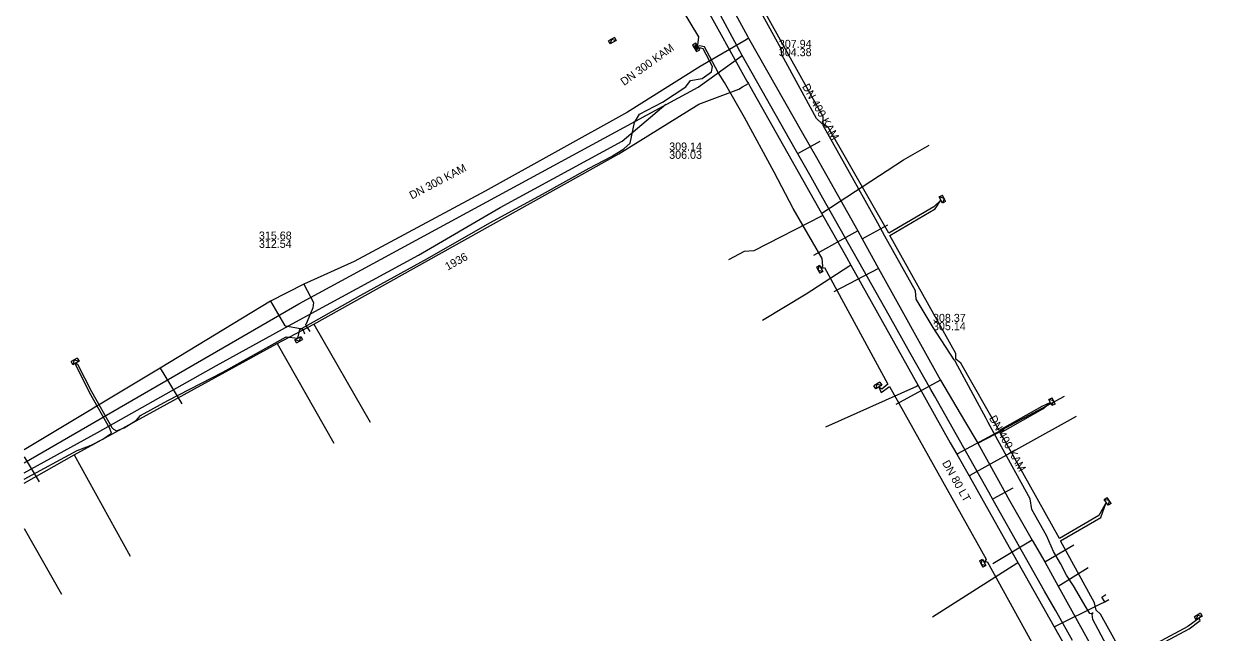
# Model space of a CAD drawing. Extents: x -600391 to -599491, y -1160176 to -1159402.
# Drawn here: x -600391 to -600270.3, y -1159795.1 to -1159734.2 of the extents above; entities that cross this region are included whole.
import ezdxf

# ---------------------------------------------------------------- set-up
doc = ezdxf.new("R2010")
doc.units = 0
for name, color, linetype in [('28', 7, 'Continuous'), ('31', 7, 'Continuous'), ('Vrstva 1', 7, 'Continuous'), ('Vrstva 12', 7, 'Continuous'), ('Vrstva 13', 7, 'Continuous'), ('Vrstva 15', 7, 'Continuous'), ('Vrstva 19', 7, 'Continuous'), ('Vrstva 42', 7, 'Continuous'), ('Vrstva 43', 7, 'Continuous'), ('Vrstva 55', 7, 'Continuous'), ('Vrstva 9', 7, 'Continuous')]:
    doc.layers.add(name, color=color, linetype=linetype)

# ---------------------------------------------------------------- blocks, each defined once
blk = doc.blocks.new('NN630')
at = {"layer": '31'}
for points in [[(0, -0.7), (-0.7, 0)], [(-0.7, -0.7), (-0.7, 0), (0.7, 0), (0.7, -0.7)], [(-0.7, -0.7), (0.7, -0.7)], [(0, -0.7), (0.7, 0)]]:
    blk.add_lwpolyline(points, dxfattribs=at)
blk = doc.blocks.new('NN620')
at = {"layer": '28'}
for points in [[(0.75, 0), (-0.75, 0)], [(-0.75, 0), (-0.75, -0.75)], [(0.75, -0.75), (0.75, 0)], [(-0.75, -0.75), (0.75, -0.75)], [(0.37, -0.18), (-0.38, -0.18)], [(-0.38, -0.18), (-0.38, -0.56)], [(-0.38, -0.56), (0.37, -0.56)], [(0.32, -0.23), (-0.33, -0.23)], [(-0.33, -0.23), (-0.33, -0.51)], [(-0.33, -0.51), (0.32, -0.51)], [(0.27, -0.27), (-0.28, -0.27)], [(-0.28, -0.27), (-0.28, -0.46)], [(-0.28, -0.46), (0.27, -0.46)], [(0.23, -0.32), (-0.23, -0.32)], [(-0.23, -0.32), (-0.23, -0.42)], [(-0.23, -0.42), (0.23, -0.42)], [(-0.19, -0.37), (0.19, -0.37)], [(0.23, -0.42), (0.23, -0.32)], [(0.27, -0.46), (0.27, -0.27)], [(0.32, -0.51), (0.32, -0.23)], [(0.37, -0.56), (0.37, -0.18)]]:
    blk.add_lwpolyline(points, dxfattribs=at)

msp = doc.modelspace()

# ---------------------------------------------------------------- linework, layer by layer
at = {"layer": 'Vrstva 1'}
for points in [[(-600311.46, -1159745.95), (-600313.69, -1159747.19)], [(-600292.17, -1159780.61), (-600294.16, -1159781.66)]]:
    msp.add_lwpolyline(points, dxfattribs=at)
at = {"layer": 'Vrstva 13'}
for p, q in [((-600318.76, -1159739.91), (-600318.61, -1159740.16)), ((-600318.9, -1159740.33), (-600318.61, -1159740.16)), ((-600318.61, -1159740.16), (-600318.46, -1159740.43)), ((-600362.04, -1159764.21), (-600356.41, -1159773.99)), ((-600365.71, -1159766.14), (-600360.04, -1159776.1)), ((-600386.02, -1159777.27), (-600380.41, -1159787.4)), ((-600391.01, -1159784.63), (-600387.27, -1159791.2))]:
    msp.add_line(p, q, dxfattribs=at)
for points in [[(-600336.73, -1159707.73), (-600331.58, -1159716.88), (-600327.91, -1159723.41), (-600324.44, -1159729.67), (-600324.17, -1159730.15), (-600323.2, -1159731.91), (-600318.76, -1159739.91)], [(-600323.58, -1159742.21), (-600319.57, -1159740.72), (-600319.19, -1159740.49), (-600318.9, -1159740.33)], [(-600318.46, -1159740.43), (-600311.31, -1159753.11), (-600311.18, -1159753.34), (-600308.82, -1159757.52), (-600308.39, -1159758.3), (-600301.63, -1159770.35), (-600298.43, -1159776.06), (-600297.79, -1159777.2), (-600296.56, -1159779.37), (-600292.54, -1159786.5), (-600291.67, -1159788.04), (-600288.04, -1159794.45), (-600287.04, -1159796.22), (-600284.44, -1159800.82), (-600282.98, -1159803.38), (-600278.58, -1159811.11), (-600272.65, -1159821.5), (-600270.29, -1159825.64)], [(-600391.01, -1159780.1), (-600386.02, -1159777.27), (-600365.71, -1159766.14), (-600362.04, -1159764.21), (-600331.56, -1159747.18), (-600323.58, -1159742.21)], [(-600311.31, -1159753.11), (-600311.18, -1159753.03), (-600303.11, -1159747.79), (-600300.55, -1159746.33)], [(-600311.18, -1159753.34), (-600311.3, -1159753.41), (-600318.06, -1159756.88), (-600319.02, -1159756.93), (-600320.61, -1159757.79)], [(-600308.39, -1159758.3), (-600308.59, -1159758.43), (-600312.83, -1159761.2), (-600317.19, -1159763.85)], [(-600301.63, -1159770.35), (-600301.82, -1159770.44), (-600310.89, -1159774.51)], [(-600297.79, -1159777.2), (-600297.67, -1159777.14), (-600287.03, -1159771.39)], [(-600296.56, -1159779.37), (-600296.43, -1159779.3), (-600285.8, -1159773.41)], [(-600291.67, -1159788.04), (-600291.79, -1159788.12), (-600300.21, -1159793.48)], [(-600288.04, -1159794.45), (-600287.91, -1159794.39), (-600283.47, -1159792.19), (-600283, -1159791.96), (-600282.59, -1159791.74)], [(-600283, -1159791.96), (-600283.28, -1159791.5), (-600282.87, -1159791.24)]]:
    msp.add_lwpolyline(points, dxfattribs=at)
at = {"layer": 'Vrstva 19'}
msp.add_line((-600391.01, -1159777.47), (-600389.5, -1159779.98), dxfattribs=at)
for points in [[(-600350.78, -1159677.57), (-600349.88, -1159678.97), (-600346.83, -1159684.41), (-600346.21, -1159685.51), (-600345.29, -1159687.14), (-600343.92, -1159689.58), (-600341.97, -1159693.07), (-600338.94, -1159698.07), (-600333.45, -1159707.31), (-600332.43, -1159710.94), (-600330.25, -1159714.8), (-600326.22, -1159721.99), (-600321.34, -1159730.55), (-600318.71, -1159735.43)], [(-600318.82, -1159735.78), (-600323.44, -1159738.44), (-600330.71, -1159743.01), (-600344.91, -1159750.92), (-600358.03, -1159757.93), (-600363.05, -1159760.22), (-600366.39, -1159761.9), (-600377.42, -1159768.62), (-600391.01, -1159776.77)], [(-600318.59, -1159735.63), (-600318.82, -1159735.78)], [(-600318.71, -1159735.43), (-600318.59, -1159735.63), (-600313.19, -1159745.12), (-600311.81, -1159747.56), (-600307.68, -1159754.89), (-600307.23, -1159755.68), (-600305.61, -1159758.66), (-600299.4, -1159769.79), (-600297, -1159773.88), (-600295.68, -1159776.09), (-600293.77, -1159779.55), (-600292.5, -1159781.84), (-600290.24, -1159785.8), (-600288.98, -1159787.98), (-600287.66, -1159790.4), (-600284.23, -1159796.59)], [(-600307.23, -1159755.68), (-600304.69, -1159754.29)], [(-600307.68, -1159754.89), (-600312.11, -1159757.34)], [(-600305.61, -1159758.66), (-600310.08, -1159760.96)], [(-600363.05, -1159760.22), (-600362.08, -1159762.04), (-600362.14, -1159762.56), (-600362.73, -1159763.94), (-600362.89, -1159764.31), (-600362.44, -1159764.95)], [(-600366.39, -1159761.9), (-600365, -1159764.32), (-600364.87, -1159764.37), (-600363.39, -1159764.65), (-600363.14, -1159764.7), (-600362.97, -1159765.18)], [(-600377.42, -1159768.62), (-600375.25, -1159772.16)], [(-600299.4, -1159769.79), (-600303.88, -1159772.23)], [(-600295.68, -1159776.09), (-600293.04, -1159774.73)], [(-600290.24, -1159785.8), (-600294.18, -1159788.15)], [(-600288.98, -1159787.98), (-600286.08, -1159786.27)], [(-600287.66, -1159790.4), (-600284.65, -1159788.54)]]:
    msp.add_lwpolyline(points, dxfattribs=at)
at = {"layer": 'Vrstva 42'}
for points in [[(-600280.77, -1159797.98), (-600274.56, -1159794.65), (-600273.47, -1159793.84), (-600273.55, -1159793.59), (-600274.69, -1159794.44), (-600280.89, -1159797.76), (-600283.41, -1159793.2), (-600283.84, -1159792.78), (-600284.02, -1159792.07), (-600287.41, -1159785.85), (-600283.39, -1159783.53), (-600282.85, -1159782.02), (-600283.57, -1159783.34), (-600287.51, -1159785.62), (-600293.42, -1159775.07), (-600289.18, -1159772.68), (-600288.42, -1159772.04), (-600289.28, -1159772.45), (-600293.54, -1159774.85), (-600297.39, -1159768.12), (-600297.88, -1159767.72), (-600297.87, -1159767.13), (-600304.49, -1159755.35), (-600299.93, -1159752.69), (-600299.37, -1159751.8), (-600300.07, -1159752.47), (-600304.59, -1159755.11), (-600310.61, -1159744.58), (-600311.13, -1159744.17), (-600311.13, -1159743.5), (-600318.84, -1159729.63)], [(-600323.75, -1159736.35), (-600323.66, -1159736.31), (-600323.58, -1159735.5), (-600325.41, -1159732.44)], [(-600311.34, -1159758.63), (-600311.17, -1159758.42), (-600311.23, -1159757.66), (-600314.15, -1159752.65), (-600316.04, -1159749.01), (-600319.01, -1159743.55), (-600320.99, -1159740.05), (-600321.65, -1159739.06), (-600322.99, -1159736.49), (-600323.51, -1159736.38), (-600323.67, -1159736.45)], [(-600381, -1159774.56), (-600379.77, -1159773.8), (-600379.38, -1159773.34), (-600376.63, -1159771.83), (-600371.15, -1159769.02), (-600364.81, -1159765.47), (-600363.66, -1159765.61), (-600363.46, -1159764.74), (-600361.56, -1159763.66), (-600357.35, -1159761.32), (-600350.7, -1159757.63), (-600344.47, -1159754.09), (-600339.21, -1159751.21), (-600334.52, -1159748.6), (-600332.3, -1159747.45), (-600331.08, -1159746.67), (-600330.44, -1159746.11), (-600330.01, -1159744.06), (-600329.49, -1159743.22), (-600327.21, -1159742.02), (-600324.87, -1159740.48), (-600324.41, -1159739.86), (-600323.24, -1159739.64), (-600322.3, -1159738.98), (-600322.19, -1159738.46), (-600323.13, -1159736.67), (-600323.37, -1159736.62), (-600323.58, -1159736.62)], [(-600311.34, -1159758.63), (-600311, -1159758.55), (-600304.66, -1159770.22), (-600305.28, -1159770.69), (-600305.58, -1159770.5), (-600305.34, -1159771.05), (-600304.52, -1159770.44), (-600294.86, -1159787.71), (-600295.05, -1159788.02), (-600294.74, -1159787.93), (-600289.43, -1159797.58)], [(-600383.13, -1159775.69), (-600382.29, -1159775.11), (-600382.44, -1159774.63), (-600384.46, -1159771.05), (-600385.85, -1159768.28), (-600385.83, -1159768.09), (-600385.66, -1159768.2), (-600384.28, -1159770.95), (-600382.26, -1159774.53), (-600382.09, -1159774.71), (-600381.78, -1159774.87), (-600381, -1159774.56)], [(-600391.01, -1159779.71), (-600385.71, -1159776.84), (-600384.32, -1159776.29), (-600383.13, -1159775.69)]]:
    msp.add_lwpolyline(points, dxfattribs=at)
at = {"layer": 'Vrstva 55'}
for points in [[(-600282.81, -1159796.3), (-600284.17, -1159793.74), (-600284.26, -1159793.21), (-600284.15, -1159793.06), (-600284.27, -1159793.16), (-600284.49, -1159793.13), (-600284.84, -1159792.54), (-600286.12, -1159790.36), (-600286.8, -1159789.31), (-600287.42, -1159788.12), (-600288.1, -1159786.94), (-600288.81, -1159785.32), (-600290.28, -1159782.72), (-600290.44, -1159781.67), (-600293.68, -1159775.8), (-600294.63, -1159774.04), (-600294.84, -1159773.64), (-600297.92, -1159767.97), (-600297.96, -1159767.87), (-600298.03, -1159767.77), (-600300.13, -1159764.54), (-600301.85, -1159761.71), (-600301.9, -1159760.86), (-600304.96, -1159755.42), (-600305.66, -1159754.11), (-600307.58, -1159750.71), (-600311.15, -1159744.36), (-600311.15, -1159744.24), (-600311.26, -1159744.16), (-600311.8, -1159743.64), (-600315.27, -1159737.29), (-600315.34, -1159736.7), (-600318.81, -1159730.34)], [(-600391.01, -1159779.08), (-600383.67, -1159775.04), (-600371.77, -1159768.34), (-600363.84, -1159763.96), (-600351.58, -1159757.31), (-600343.41, -1159752.54), (-600331.24, -1159745.92), (-600326.86, -1159742.22)]]:
    msp.add_lwpolyline(points, dxfattribs=at)
at = {"layer": 'Vrstva 9'}
for p, q in [((-600323.62, -1159740.51), (-600319.23, -1159737.35)), ((-600363.56, -1159762.18), (-600323.62, -1159740.51)), ((-600391.01, -1159778.08), (-600363.56, -1159762.18))]:
    msp.add_line(p, q, dxfattribs=at)
for points in [[(-600319.23, -1159737.35), (-600322.13, -1159731.94), (-600326.25, -1159724.28), (-600329.99, -1159717.32), (-600331.85, -1159713.86), (-600334.86, -1159708.24)], [(-600302.46, -1159767.03), (-600304.55, -1159763.33), (-600311.16, -1159751.62), (-600312.34, -1159749.53), (-600313.95, -1159746.7), (-600319.23, -1159737.35)], [(-600286.22, -1159795.83), (-600287.92, -1159792.81), (-600289.01, -1159790.9), (-600294.13, -1159781.81), (-600294.58, -1159781.01), (-600300, -1159771.38), (-600300.37, -1159770.73), (-600302.46, -1159767.03)]]:
    msp.add_lwpolyline(points, dxfattribs=at)

# ---------------------------------------------------------------- block references
at = {"layer": 'Vrstva 43'}
for name, p, xscale, yscale, rotation in [('NN630', (-600332.13, -1159736.02), 0.5, 0.5, -150.00000000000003), ('NN620', (-600323.67, -1159736.45), 0.5, 0.5, -59.00000000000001), ('NN630', (-600299.37, -1159751.8), 0.5, 0.5, 117), ('NN630', (-600311.34, -1159758.63), 0.5, 0.5, -59.99999999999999), ('NN630', (-600363.66, -1159765.61), 0.5, 0.5, 29.00000000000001), ('NN630', (-600385.83, -1159768.09), 0.5000000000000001, 0.4999999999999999, -151), ('NN630', (-600305.58, -1159770.5), 0.5, 0.5, -148), ('NN630', (-600288.42, -1159772.04), 0.5000000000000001, 0.5000000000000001, 116.00000000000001), ('NN630', (-600282.85, -1159782.02), 0.5, 0.5, 123.00000000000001), ('NN630', (-600295.05, -1159788.02), 0.49999999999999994, 0.5000000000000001, -62.00000000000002), ('NN630', (-600273.55, -1159793.59), 0.5, 0.5, -149.00000000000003)]:
    msp.add_blockref(name, p, dxfattribs=dict(at, xscale=xscale, yscale=yscale, rotation=rotation))

# ---------------------------------------------------------------- texts
at = {"layer": 'Vrstva 12'}
for s, rotation, p in [('DN 300 KAM', 35.7446, (-600331.04, -1159740.41)), ('DN 400 KAM', 299.467, (-600313.27, -1159740.45)), ('DN 300 KAM', 27.7312, (-600352.25, -1159751.75)), ('DN 400 KAM', 299.4066, (-600294.59, -1159773.6))]:
    msp.add_text(s, height=0.8, rotation=rotation, dxfattribs=at).set_placement(p)
for s, p in [('307.94', (-600315.57, -1159736.59)), ('304.38', (-600315.57, -1159737.42)), ('309.14', (-600326.53, -1159746.85)), ('306.03', (-600326.53, -1159747.68)), ('315.68', (-600367.54, -1159755.75)), ('312.54', (-600367.54, -1159756.58)), ('308.37', (-600300.16, -1159763.98)), ('305.14', (-600300.16, -1159764.81))]:
    msp.add_text(s, height=0.8, dxfattribs=at).set_placement(p)
at = {"layer": 'Vrstva 15'}
for s, rotation, p in [('1936', 28.7052, (-600348.67, -1159758.86)), ('DN 80 LT', 299.4177, (-600299.28, -1159778.08))]:
    msp.add_text(s, height=0.8, rotation=rotation, dxfattribs=at).set_placement(p)

doc.saveas('drawing.dxf')
